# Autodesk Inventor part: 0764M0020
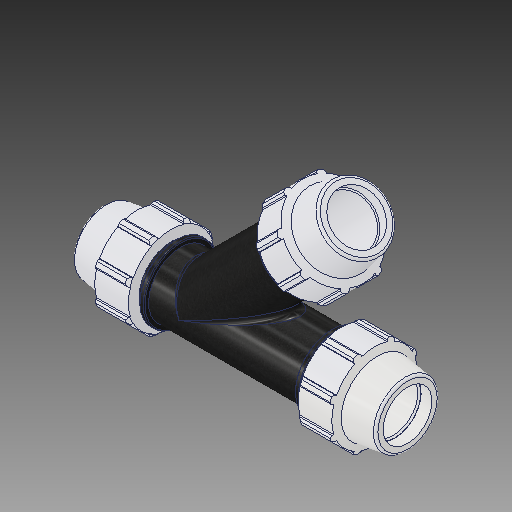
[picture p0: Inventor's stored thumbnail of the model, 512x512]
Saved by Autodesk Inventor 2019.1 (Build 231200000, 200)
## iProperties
Created: 2017-02
Part Number: 0764M0020
Material: PVC-Piping
Description: PLASSON 45° TEE 2'' - 2'' - 2''
Document SubType Name: Modeling
Designer: KIM
Mass: 92.6774 g
Surface Area: 199.44 cm^2
Volume: 66.1981 cm^3
Density: 1.4 g/cm^3
Appearance: PTFE
Author: Кирилл
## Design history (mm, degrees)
derived "0764M0.ipt"
feature "Solid1::0764M0.ipt"
feature "Solid3::0764M0.ipt"
tag "TaggingFeature1"
body "Solid1"
other parameters: "d2" = 60.1, "d4" = 15.53633, "d5" = 37.2872, "d7" = 113.03, "d11" = 6.21453, "d13" = 120 deg, "d14" = 78.13, "d15" = 8 deg, "d16" = 90.424, "d18" = 3.005, "d19" = 35 deg, "d20" = 17.5 deg, "d21" = 105.1179, "d23" = 0, "d25" = 360 deg, "d27" = 2.2606, "d33" = 1.202, "d42" = 44.74464, "d43" = 3.3909, "d46" = 1.803, "d68" = 5.59308, "d91" = 79.121, "d93" = 109.982, "d95" = 54.09, "d134" = 186.436, "d138" = 45 deg, "d141" = 207.01, "d144" = 0, "d146" = 0, "d150" = 3.005, "d158" = 6.01, "d165" = 241.9604, "d166" = 105.1179, "d167" = 35 deg, "d168" = 17.5 deg, "d170" = 0, "d172" = 360 deg, "d174" = 3.3909, "d177" = 2.2606, "d_" = 60.1, "E_" = 113.03, "A_" = 207.01, "l_" = 109.982, "H_" = 372.872
